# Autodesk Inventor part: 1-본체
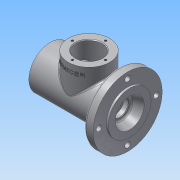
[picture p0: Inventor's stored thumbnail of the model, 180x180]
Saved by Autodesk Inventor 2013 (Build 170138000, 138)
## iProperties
Created: 2016-08
Part Number: 1-본체
Material: 알루미늄 6061
Document SubType Name: Modeling
Designer: Administrator
Density: 2.71 g/cm^3
Mass: 766.33 g
Surface Area: 624.874 cm^2
Volume: 282.779 cm^3
Author: Administrator
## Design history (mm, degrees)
sketch "스케치1"
  geometry: L1 (-57.5, 0)-(57.5, 0); L2 (-57.5, 31)-(41.5, 31); L3 (41.5, 31)-(41.5, 50); L4 (41.5, 50)-(54.5, 50); L5 (54.5, 50)-(54.5, 31); L6 (54.5, 31)-(57.5, 31); L7 (57.5, 21)-(57.5, 31); L8 (-57.5, 31)-(-57.5, 21); L9 (-57.5, 21)-(-48.5, 21); L10 (-48.5, 21)-(-48.5, 24); L11 (-48.5, 24)-(-45.5, 24); L12 (-45.5, 24)-(-45.5, 20); L13 (-45.5, 20)-(-38.25, 20); L14 (-38.25, 20)-(-38.25, 17.5); L15 (-38.25, 17.5)-(-33.25, 17.5); L16 (-33.25, 17.5)-(-33.25, 18.5); L17 (-31.5, 18.5)-(-31.5, 17.5); L18 (-31.5, 17.5)-(-21.5, 17.5); L19 (-20.5, 18.5)-(-20.5, 23); L20 (-17.5, 26)-(14.5, 26); L21 (17.5, 23)-(17.5, 18.5); L22 (18.5, 17.5)-(28.2, 17.5); L23 (28.5, 17.2)-(28.5, 16.5); L24 (28.5, 16.5)-(30.5, 16.5); L25 (33.5, 13.5)-(33.5, 10); L26 (33.5, 10)-(36.2, 10); L27 (36.2, 10)-(36.2, 12.2); L28 (36.5, 12.5)-(42.8, 12.5); L29 (43.5, 12.904)-(43.5, 13.886); L30 (45.491, 16.711)-(57.5, 21); L31 (-33.25, 18.5)-(-31.5, 18.5); L32 (-20.5, 18.5)-(-21.5, 17.5); L33 (17.5, 18.5)-(18.5, 17.5); L34 (42.8, 12.5)-(43.5, 12.904); A1 r 3 centre (-17.5, 23) between (-17.5, 26) and (-20.5, 23); A2 r 3 centre (14.5, 23) between (17.5, 23) and (14.5, 26); A3 r 3 centre (30.5, 13.5) between (33.5, 13.5) and (30.5, 16.5); A4 r 0.3 centre (28.2, 17.2) between (28.5, 17.2) and (28.2, 17.5); A5 r 0.3 centre (36.5, 12.2) between (36.5, 12.5) and (36.2, 12.2); A6 r 3 centre (46.5, 13.886) between (45.491, 16.711) and (43.5, 13.886); 11 further points
  constraints: 68 end point, 22 parallel, 18 point on line, 12 point on circle, 12 tangent, 6 centre point, 6 perpendicular, 2 horizontal, 2 vertical alignment, 1 coincident, 1 equal radius, 1 midpoint
  dimensions: "d0" = 115 distance of L1.start L1.end; "d2" = 62 diameter of L2 L1; "d3" = 100 diameter of L4 L1; "d4" = 13 distance of L3.end L4.end; "d5" = 3 distance between parallel lines of L5 L7; "d6" = 62 diameter of L6 L1; "d7" = 52 diameter of L20 L1; "d8" = 42 diameter of L9 L1; "d9" = 48 diameter of L11 L1; "d12" = 40 diameter of L13 L1; "d13" = 35 diameter of L15 L1; "d15" = 35 diameter of L18 L1; "d19" = 42 diameter of L7.start L1; "d20" = 14 horizontal distance of point (43.5, 16) L7.start; "d21" = 32 diameter of point (43.5, 16) L1; "d22" = 7.3 distance of point (36.2, 12.5) point (43.5, 12.5); "d23" = 25 diameter of L28 L1; "d24" = 2.7 distance of L25.end L26.end; "d25" = 20 diameter of L26 L1; "d26" = 5 distance of L23.end point (33.5, 16.5); "d27" = 33 diameter of L24 L1; "d28" = 35 diameter of L22 L1; "d29" = 60 distance of point (28.5, 17.5) L17.end; "d30" = 38 distance of point (-20.5, 26) point (17.5, 26); "d31" = 5 distance of L14.end L15.end; "d32" = 1.75 distance of L16.end L17.start; "d33" = 12 distance between parallel lines of L8 L12; "d34" = 3 distance of L10.end L11.end; "d35" = 37 diameter of L31 L1; "d36" = 11 distance of L17.end point (-20.5, 17.5); "d37" = 3 radius of A1; "d38" = 1 distance of L19.start point (-20.5, 17.5); "d39" = 1 distance of L18.end point (-20.5, 17.5) (= d38); "d40" = 1 distance of L21.end point (17.5, 17.5); "d41" = 1 distance of L22.start point (17.5, 17.5) (= d40); "d42" = 3 radius of A3; "d43" = 0.3 radius of A4; "d44" = 0.3 radius of A5; "d45" = 0.7 distance of L28.end point (43.5, 12.5); "d46" = 30 deg angle of L28 L34; "d47" = 3 radius of A6
revolve "회전1" sketch "스케치1" stored, may be unused: angle "d48" = 90 deg
feature "스레드1" dims "d49" = 10, "d50" = 0
node "작업 평면1"
sketch "스케치2"
  geometry: L1 (-57.5, -31)-(-57.5, 31) reference; C1 r 30 at (-1.5, 0); 2 further points
  constraints: 1 centre point, 1 horizontal alignment, 1 midpoint
  dimensions: "d52" = 60 diameter of C1; "d54" = 56 distance from line of C1.centre L1
extrude "돌출1" join sketch "스케치2" stored distance "d55" = 10; taper "d56" = 0 deg
sketch "스케치3"
  geometry: C1 r 30 at (0, 0) reference; C2 r 19 at (0, 0); 1 further point
  constraints: 1 centre point, 1 coincident
  dimensions: "d57" = 38 diameter of C2
extrude "돌출2" cut sketch "스케치3" distance "d59" = 50; taper "d60" = 0 deg
sketch "스케치4"
  geometry: C1 r 50 at (0, 0) reference; C2 r 31 at (0, 0) reference; C3 r 4 at (0, 41.5); C4 r 4 at (-41.5, 0); C5 r 4 at (0, -41.5); C6 r 4 at (41.5, 0); A1 r 41.5 centre (0, 0) between (0, 41.5) and (-41.5, 0)
  constraints: 5 centre point, 4 point on circle, 3 equal radius, 2 horizontal alignment, 2 vertical alignment, 1 coincident
  dimensions: "d61" = 83 diameter of A1; "d63" = 8 diameter of C3
extrude "돌출3" cut sketch "스케치4" stored distance "d64" = 10; taper "d65" = 0 deg
sketch "스케치5"
  geometry: C1 r 19 at (0, 0) reference; C2 r 30 at (0, 0) reference; A1 r 24 centre (0, 0) between (0, 24) and (-24, 0); 3 further points
  constraints: 4 point on circle, 2 horizontal alignment, 2 vertical alignment, 1 centre point, 1 coincident
  dimensions: "d66" = 48 diameter of A1
hole "구멍1" sketch "스케치5" at (0, 24), (-24, 0), (0, -24), (24, 0) diameter "d68" = 3.242; stored, may be unused: countersink angle "d72" = 90 deg, drill point angle "d74" = 118 deg; dims "d69" = 8, "d70" = 4, "d71" = 2, "d73" = 10
fillet "모깎기1" dims "d75" = 3
chamfer "모따기1" distance "d76" = 1; stored, may be unused: second distance "d77" = 2, angle "d78" = 45 deg
fillet "모깎기2" dims "d79" = 3
node "작업 평면2"
sketch "스케치6"
  geometry: L1 (-31.5, 49)-(28.5, 49) reference; 3 further points
  constraints: 1 midpoint, 1 vertical alignment, 1 other
  dimensions: "d81" = 10 distance from line of point (-1.5, 39) L1
feature "엠보싱1" sketch "스케치6" dims "d82" = 0.5, "d83" = 0
fillet "모깎기3" dims "d84" = 3
node "솔리드1"
other parameters: "d51" = 49
